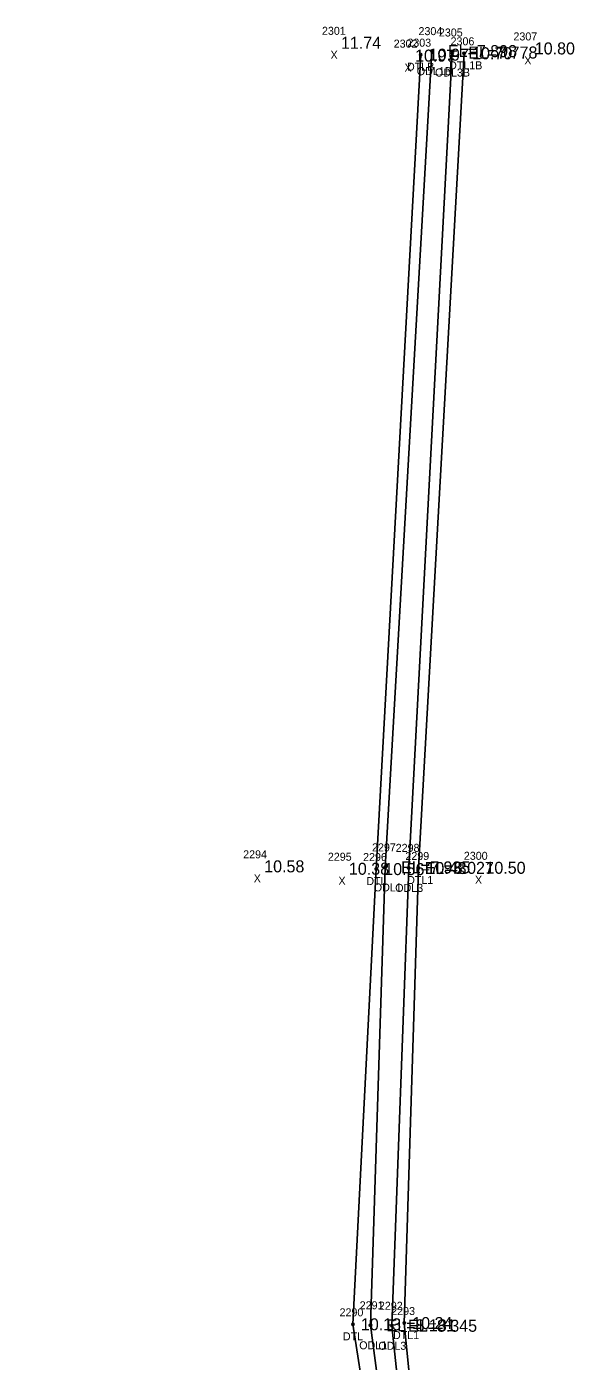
# Model space of a CAD drawing. Extents: x 2042117 to 2045853, y 303080 to 309569.
# Drawn here: x 2044376.7 to 2044445.2, y 305116.8 to 305283.6 of the extents above; entities that cross this region are included whole.
import ezdxf

# ---------------------------------------------------------------- set-up
doc = ezdxf.new("R2010")
doc.units = 0
for name, color, linetype in [('RD_EX_H2O', 7, 'Continuous'), ('RD_EX_H2O_txCode', 7, 'Continuous'), ('RD_EX_Misc_txCode', 7, 'Continuous'), ('RD_EX_TX_H2O_ELEV', 7, 'Continuous'), ('RD_EX_TX_Misc_ELEV', 7, 'Continuous'), ('RD_SMD_Locator', 7, 'Continuous')]:
    doc.layers.add(name, color=color, linetype=linetype)

msp = doc.modelspace()

# ---------------------------------------------------------------- linework, layer by layer
at = {"layer": 'RD_EX_H2O'}
for points in [[(2044376.72, 305085.18), (2044400.19, 305088.25), (2044423.37, 305086.53), (2044423.86, 305089.84), (2044419.71, 305121.34), (2044421.53, 305178.54), (2044427.38, 305280.5)], [(2044377.7, 305092.63), (2044379.12, 305090.54), (2044400.04, 305092.04), (2044422.37, 305090.27), (2044417.51, 305121.46), (2044420.43, 305178.33), (2044425.99, 305280.06)], [(2044441.36, 305088.55), (2044426.83, 305088.6), (2044425.44, 305092.07), (2044422.39, 305121.28), (2044424.49, 305178.48), (2044429.93, 305280.33)], [(2044441.65, 305090.99), (2044426.95, 305091.14), (2044423.93, 305121.62), (2044425.7, 305178.46), (2044431.41, 305280.23)]]:
    msp.add_lwpolyline(points, dxfattribs=at)
at = {"layer": 'RD_SMD_Locator'}
for centre in [(2044427.38, 305280.5), (2044429.93, 305280.33), (2044425.99, 305280.06), (2044431.41, 305280.23), (2044420.43, 305178.33), (2044421.53, 305178.54), (2044424.49, 305178.48), (2044425.7, 305178.46), (2044417.51, 305121.46), (2044419.71, 305121.34), (2044422.39, 305121.28), (2044423.93, 305121.62)]:
    msp.add_circle(centre, 0.15, dxfattribs=at)

# ---------------------------------------------------------------- texts
at = {"layer": 'RD_EX_H2O_txCode'}
for s, p in [('2303', (2044424.32, 305281.06)), ('2304', (2044425.71, 305282.5)), ('2305', (2044428.26, 305282.33)), ('2306', (2044429.72, 305281.23)), ('DTLB', (2044424.27, 305278.06)), ('DTL1B', (2044429.53, 305278.23)), ('ODL1B', (2044425.5, 305277.5)), ('ODL3B', (2044427.77, 305277.33)), ('2297', (2044419.9, 305180.54)), ('2298', (2044422.86, 305180.48)), ('2299', (2044424.07, 305179.46)), ('2296', (2044418.78, 305179.33)), ('DTL', (2044419.19, 305176.33)), ('DTL1', (2044424.29, 305176.46)), ('ODL1', (2044420.12, 305175.54)), ('ODL3', (2044422.8, 305175.48)), ('2291', (2044418.36, 305123.34)), ('2292', (2044420.76, 305123.28)), ('2290', (2044415.84, 305122.46)), ('2293', (2044422.3, 305122.62)), ('DTL', (2044416.26, 305119.46)), ('DTL1', (2044422.52, 305119.62)), ('ODL1', (2044418.3, 305118.34)), ('ODL3', (2044420.69, 305118.28))]:
    msp.add_text(s, height=1, dxfattribs=at).set_placement(p)
at = {"layer": 'RD_EX_Misc_txCode'}
for s, p in [('2301', (2044413.64, 305282.54)), ('2307', (2044437.58, 305281.84)), ('X', (2044414.71, 305279.54)), ('2302', (2044422.61, 305280.94)), ('X', (2044423.96, 305277.94)), ('X', (2044438.94, 305278.84)), ('2294', (2044403.79, 305179.67)), ('2295', (2044414.38, 305179.37)), ('2300', (2044431.38, 305179.49)), ('X', (2044405.11, 305176.67)), ('X', (2044415.7, 305176.37)), ('X', (2044432.77, 305176.49))]:
    msp.add_text(s, height=1, dxfattribs=at).set_placement(p)
at = {"layer": 'RD_EX_TX_H2O_ELEV'}
for s, p in [('10.97', (2044426.99, 305279.31)), ('EL=7.898', (2044429.38, 305279.75)), ('EL=7.778', (2044431.93, 305279.58)), ('10.70', (2044432.41, 305279.48)), ('10.56', (2044421.43, 305177.58)), ('EL=7.935', (2044423.53, 305177.79)), ('EL=8.027', (2044426.49, 305177.73)), ('10.43', (2044426.7, 305177.71)), ('10.13', (2044418.51, 305120.71)), ('EL=8.131', (2044421.71, 305120.59)), ('EL=8.345', (2044424.39, 305120.53)), ('10.24', (2044424.93, 305120.87))]:
    msp.add_text(s, height=1.5, dxfattribs=at).set_placement(p)
at = {"layer": 'RD_EX_TX_Misc_ELEV'}
for s, p in [('11.74', (2044416.02, 305280.79)), ('10.97', (2044425.28, 305279.19)), ('10.80', (2044440.25, 305280.09)), ('10.58', (2044406.42, 305177.92)), ('10.38', (2044417.01, 305177.62)), ('10.50', (2044434.08, 305177.74))]:
    msp.add_text(s, height=1.5, dxfattribs=at).set_placement(p)

doc.saveas('drawing.dxf')
